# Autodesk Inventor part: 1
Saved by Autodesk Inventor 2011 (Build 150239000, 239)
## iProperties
Created: 2012-07
Part Number: 1
Document SubType Name: Modeling
Designer: R.JANSSEN
Mass: 5518.46 g
Surface Area: 7094.36 cm^2
Volume: 5518.46 cm^3
Density: 1 g/cm^3
Author: R.JANSSEN
Translation Standard: STEP AP203
FileName: //expscmdclustefs.cadenas.external/client_exchange/iodir/jobs/output/wkb47459197_no0//0//151580_DNG_6_12_PPV_A_2_03.stp
PostProcessor: Build: 239, Release: 2011 RTM - Date: Wed 02/17/2010
Sent Units: millimeter
Uncertainty: 1.0000000000000002e-06
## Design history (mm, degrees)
feature "Base1"
node "1"
